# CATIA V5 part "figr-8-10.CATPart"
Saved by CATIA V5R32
Part number: Part2
Bounding box of the stored display mesh (mm): x -37.886 to 37.886, y -61.415 to 61.415, z 29 to 58
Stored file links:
  D:\PROJECTS\Project 2022\CATIA V5 6R 2022\Resources\Part Files\c08_catia_v5_6r2022_prt\figr-8-10.CATPart
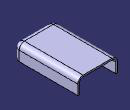
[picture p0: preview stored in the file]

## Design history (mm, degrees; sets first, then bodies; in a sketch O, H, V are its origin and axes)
Body1 (main body)
  Sketch1 on xy-plane, origin (0, 0, 0), H (1, 0, 0), V (0, 1, 0)
    line L1 (37.8862, 61.4155) -> (37.8862, -61.4155)
    line L2 (37.8862, -61.4155) -> (-37.8862, -61.4155)
    line L3 (-37.8862, -61.4155) -> (-37.8862, 61.4155)
    line L4 (-37.8862, 61.4155) -> (37.8862, 61.4155)
    vertical: L1 V, L3 V
    horizontal: L2 H, L4 H
    equidistance: L1 L3 O, L2 L4 O
  Pad1: profile Sketch1, direction (0, 0, 1), length 29
  Fillet1: radius 10, on edge [face of Pad1 | face of Pad1] (x5)
  Shell1: ExtOffset 0, Face (face of Pad1; face of Pad1), IntOffset 3
  Symmetry1: Reference face of Pad1, ToTransfor Shell1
